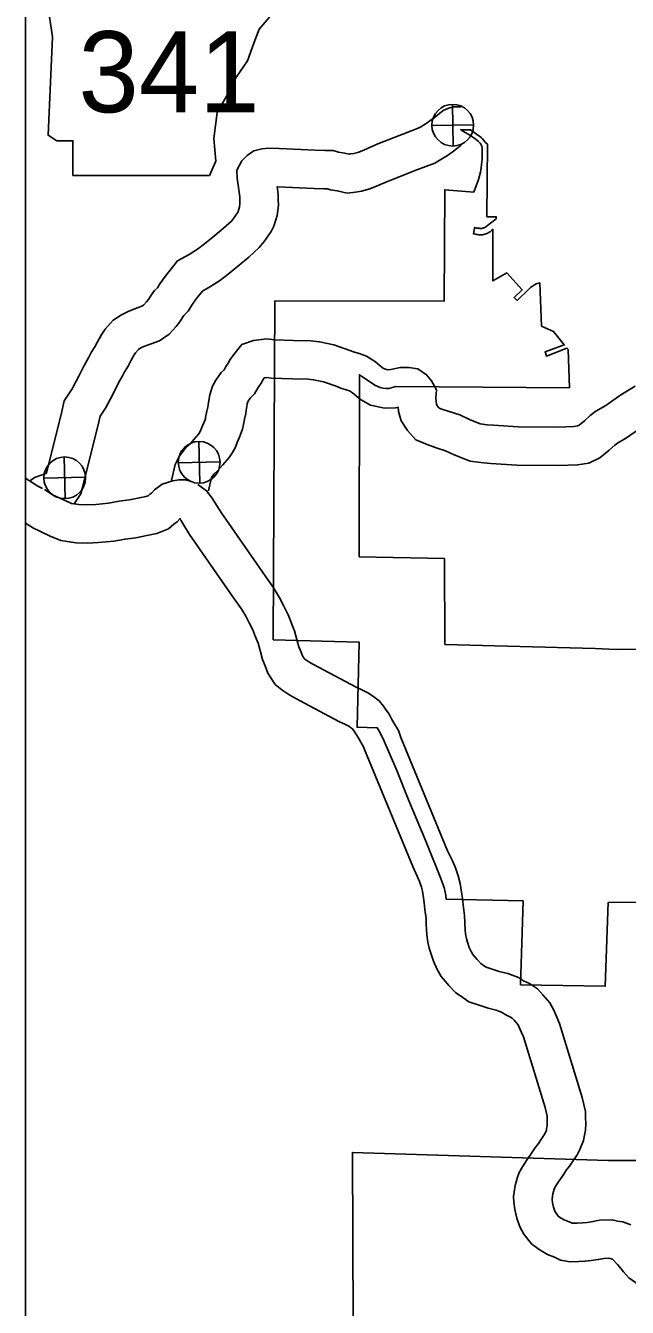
# Model space of a CAD drawing. Extents: x 1377389 to 1380723, y 1168351 to 1170484.
# Drawn here: x 1377549.8 to 1377596.7, y 1170176.4 to 1170276.6 of the extents above; entities that cross this region are included whole.
import ezdxf

# ---------------------------------------------------------------- set-up
doc = ezdxf.new("R2010")
doc.units = 0
doc.layers.add('B_Fill', color=7, linetype='Continuous')
doc.layers.add('B_Text', color=7, linetype='Continuous')

msp = doc.modelspace()

# ---------------------------------------------------------------- linework, layer by layer
at = {"layer": 'B_Fill'}
for p, q in [((1377583.15, 1170267.18), (1377583.08, 1170270.43)), ((1377581.49, 1170268.77), (1377584.74, 1170268.84)), ((1377563.35, 1170240.82), (1377563.27, 1170244.07)), ((1377552.85, 1170239.61), (1377552.77, 1170242.87)), ((1377561.68, 1170242.41), (1377564.94, 1170242.48)), ((1377551.18, 1170241.2), (1377554.44, 1170241.28))]:
    msp.add_line(p, q, dxfattribs=at)
msp.add_lwpolyline([(1377551.09, 1170280.78), (1377551.85, 1170275.7), (1377551.51, 1170268.01), (1377552.19, 1170267.58), (1377553.45, 1170267.58), (1377553.45, 1170264.88), (1377564.11, 1170264.88), (1377564.62, 1170265.98), (1377564.45, 1170267.75), (1377564.7, 1170269.78), (1377565.63, 1170271.39), (1377566.23, 1170272.57), (1377567.07, 1170273.84), (1377567.58, 1170275.2), (1377568, 1170276.3), (1377568.76, 1170277.23), (1377568.93, 1170277.82), (1377568.6, 1170278.24), (1377565.97, 1170278.24), (1377566.57, 1170279.43), (1377566.65, 1170280.19), (1377566.3, 1170280.77)], close=True, dxfattribs=at)
for points in [[(1377550.13, 1170241.03), (1377550.45, 1170241.26), (1377551.04, 1170241.48), (1377551.38, 1170241.6), (1377552.59, 1170246.41), (1377552.77, 1170247.25), (1377553.39, 1170248.19), (1377553.5, 1170248.4), (1377553.91, 1170249.18), (1377554.34, 1170250.03), (1377554.66, 1170250.62), (1377554.87, 1170251.03), (1377555.17, 1170251.48), (1377555.34, 1170251.82), (1377555.66, 1170252.4), (1377555.96, 1170252.85), (1377556.58, 1170253.55), (1377557.23, 1170253.99), (1377557.81, 1170254.27), (1377558.55, 1170254.54), (1377558.84, 1170254.65), (1377558.97, 1170254.74), (1377559.2, 1170254.99), (1377559.34, 1170255.18), (1377559.55, 1170255.51), (1377559.83, 1170255.87), (1377560.05, 1170256.1), (1377560.24, 1170256.41), (1377560.65, 1170256.97), (1377560.84, 1170257.21), (1377561.61, 1170258.19), (1377562.53, 1170258.7), (1377563.18, 1170259.11), (1377563.72, 1170259.52), (1377564.54, 1170260.18), (1377565.21, 1170260.75), (1377565.82, 1170261.31), (1377565.98, 1170261.5), (1377566.34, 1170262.03), (1377566.35, 1170262.06), (1377566.46, 1170262.41), (1377566.49, 1170262.64), (1377566.48, 1170262.9), (1377566.48, 1170263.21), (1377566.27, 1170264.67), (1377566.26, 1170265.28), (1377566.63, 1170266.01), (1377567.05, 1170266.44), (1377567.58, 1170266.79), (1377568.21, 1170266.96), (1377568.74, 1170267), (1377569.55, 1170266.99), (1377572.37, 1170266.84), (1377573.11, 1170266.83), (1377573.76, 1170266.81), (1377574.18, 1170266.7), (1377574.67, 1170266.62), (1377575.03, 1170266.54), (1377575.11, 1170266.55), (1377575.38, 1170266.59), (1377575.69, 1170266.67), (1377576.17, 1170266.86), (1377576.8, 1170267.14), (1377577.39, 1170267.4), (1377579.21, 1170268.1), (1377579.95, 1170268.39), (1377580.42, 1170268.56), (1377580.61, 1170268.67), (1377581.02, 1170268.93), (1377581.31, 1170269.13), (1377581.66, 1170269.38), (1377581.93, 1170269.61), (1377582.35, 1170269.96), (1377582.73, 1170270.11), (1377583.14, 1170270.24), (1377583.52, 1170270.24), (1377583.76, 1170270.24)], [(1377585.09, 1170267.55), (1377584.82, 1170267.77), (1377584.61, 1170267.92), (1377584.32, 1170268.1), (1377584.08, 1170268.24), (1377583.73, 1170268.44), (1377584.5, 1170268.43), (1377584.76, 1170268.25), (1377584.97, 1170268.11), (1377585.07, 1170268.03), (1377585.19, 1170267.93), (1377585.32, 1170267.83), (1377585.41, 1170267.75), (1377585.5, 1170267.64), (1377585.66, 1170267.46), (1377585.81, 1170267.31), (1377585.78, 1170261.64), (1377586.51, 1170261.64), (1377586.51, 1170261.49), (1377585.82, 1170260.95), (1377585.72, 1170260.87), (1377585.69, 1170260.85), (1377585.64, 1170260.82), (1377585.58, 1170260.79), (1377585.53, 1170260.77), (1377585.48, 1170260.75), (1377585.42, 1170260.74), (1377585.4, 1170260.74), (1377585.37, 1170260.73), (1377585.34, 1170260.73), (1377585.31, 1170260.73), (1377585.26, 1170260.73), (1377585.23, 1170260.73), (1377585.18, 1170260.74), (1377585.13, 1170260.74), (1377585.04, 1170260.75), (1377585, 1170260.76), (1377584.94, 1170260.77), (1377584.82, 1170260.81), (1377584.81, 1170260.76), (1377584.79, 1170260.63), (1377584.75, 1170260.43), (1377584.72, 1170260.31), (1377584.82, 1170260.29), (1377584.9, 1170260.27), (1377584.96, 1170260.26), (1377585.02, 1170260.25), (1377585.13, 1170260.24), (1377585.19, 1170260.23), (1377585.23, 1170260.23), (1377585.28, 1170260.23), (1377585.33, 1170260.23), (1377585.38, 1170260.23), (1377585.43, 1170260.23), (1377585.51, 1170260.25), (1377585.61, 1170260.27), (1377585.7, 1170260.3), (1377585.79, 1170260.33), (1377585.88, 1170260.38), (1377585.96, 1170260.43), (1377586.02, 1170260.47), (1377586.14, 1170260.57), (1377586.25, 1170260.66), (1377586.25, 1170256.63), (1377587.32, 1170257.25), (1377588.54, 1170255.94), (1377587.9, 1170255.33), (1377588.13, 1170255.1), (1377589.05, 1170255.99), (1377589.19, 1170256.11), (1377589.34, 1170256.23), (1377589.49, 1170256.33), (1377589.63, 1170256.41), (1377589.7, 1170256.43), (1377589.92, 1170256.47), (1377590.04, 1170253.09), (1377590.98, 1170252.67), (1377591.82, 1170251.63), (1377590.32, 1170251.08), (1377590.43, 1170250.76), (1377592.02, 1170251.38), (1377592.12, 1170251.26), (1377592.22, 1170248.26), (1377578.66, 1170248.38), (1377578.3, 1170248.26), (1377578.11, 1170248.23), (1377577.9, 1170248.22), (1377577.64, 1170248.25), (1377577.43, 1170248.3), (1377577.27, 1170248.37), (1377577.08, 1170248.45), (1377576.88, 1170248.58), (1377576.06, 1170249.13), (1377575.82, 1170249.29), (1377575.8, 1170235.07), (1377582.47, 1170234.93), (1377582.48, 1170228.21)], [(1377553.55, 1170239.26), (1377553.6, 1170239.28), (1377554.07, 1170239.99), (1377554.2, 1170240.49), (1377555.5, 1170245.72), (1377555.58, 1170246.05), (1377556, 1170246.69), (1377556.17, 1170247.03), (1377556.58, 1170247.8), (1377557, 1170248.65), (1377557.31, 1170249.22), (1377557.45, 1170249.48), (1377557.77, 1170249.97), (1377558.01, 1170250.44), (1377558.22, 1170250.84), (1377558.33, 1170251), (1377558.58, 1170251.27), (1377558.74, 1170251.39), (1377558.99, 1170251.51), (1377559.57, 1170251.72), (1377560.2, 1170251.95), (1377560.96, 1170252.46), (1377561.5, 1170253.07), (1377561.79, 1170253.43), (1377562, 1170253.77), (1377562.12, 1170253.92), (1377562.44, 1170254.26), (1377562.73, 1170254.74), (1377563.03, 1170255.15), (1377563.19, 1170255.35), (1377563.59, 1170255.85), (1377564.05, 1170256.11), (1377564.89, 1170256.64), (1377565.56, 1170257.15), (1377566.44, 1170257.86), (1377567.19, 1170258.49), (1377568, 1170259.24), (1377568.39, 1170259.71), (1377568.92, 1170260.49), (1377569.14, 1170260.91), (1377569.4, 1170261.75), (1377569.51, 1170262.54), (1377569.48, 1170262.98), (1377569.48, 1170263.4), (1377569.4, 1170263.99), (1377569.45, 1170263.99), (1377572.28, 1170263.84), (1377573.04, 1170263.83), (1377573.33, 1170263.82), (1377573.55, 1170263.76), (1377574.09, 1170263.67), (1377574.87, 1170263.49), (1377575.51, 1170263.57), (1377575.98, 1170263.64), (1377576.64, 1170263.82), (1377577.34, 1170264.1), (1377578, 1170264.39), (1377578.54, 1170264.62), (1377580.3, 1170265.31), (1377581, 1170265.58), (1377581.7, 1170265.83), (1377582.17, 1170266.11), (1377582.69, 1170266.43), (1377583.05, 1170266.69), (1377583.51, 1170267.02), (1377583.77, 1170267.23)], [(1377601.86, 1170208.09), (1377595.23, 1170208.04), (1377595.02, 1170201.5), (1377588.4, 1170201.61), (1377588.6, 1170208.18), (1377582.6, 1170208.3), (1377582.56, 1170208.6), (1377582.51, 1170208.84), (1377582.43, 1170209.23), (1377582.32, 1170209.55), (1377582.17, 1170209.91), (1377581, 1170212.83), (1377579.64, 1170216.06), (1377578.73, 1170218.35), (1377578.18, 1170219.68), (1377577.76, 1170220.65), (1377577.46, 1170221.25), (1377577.25, 1170221.63), (1377577.21, 1170221.69), (1377575.64, 1170221.74), (1377575.79, 1170228.4), (1377569.09, 1170228.58), (1377569.22, 1170255.08), (1377582.44, 1170255.05), (1377582.48, 1170263.75), (1377584.75, 1170263.57), (1377585.12, 1170264.56), (1377585.2, 1170264.84), (1377585.27, 1170265.13), (1377585.33, 1170265.47), (1377585.36, 1170265.74), (1377585.4, 1170266.14), (1377585.41, 1170266.49), (1377585.41, 1170266.77), (1377585.4, 1170267.03), (1377585.38, 1170267.13), (1377585.35, 1170267.21), (1377585.3, 1170267.32), (1377585.25, 1170267.39), (1377585.09, 1170267.55)], [(1377561.14, 1170241.02), (1377561.43, 1170242.27), (1377561.74, 1170242.91), (1377562.26, 1170243.61), (1377562.63, 1170243.93), (1377562.9, 1170244.24), (1377563.25, 1170244.64), (1377563.32, 1170244.74), (1377563.38, 1170244.87), (1377563.56, 1170245.31), (1377563.69, 1170245.6), (1377563.79, 1170245.85), (1377563.81, 1170245.96), (1377563.91, 1170246.44), (1377563.98, 1170246.77), (1377564.01, 1170246.95), (1377564.06, 1170247.28), (1377564.13, 1170247.73), (1377564.36, 1170248.41), (1377564.62, 1170248.88), (1377565.02, 1170249.46), (1377565.25, 1170249.68), (1377565.39, 1170249.93), (1377565.58, 1170250.2), (1377565.74, 1170250.49), (1377566.01, 1170250.88), (1377566.63, 1170251.66), (1377567.54, 1170251.96), (1377568.6, 1170252.1), (1377569.19, 1170252.02), (1377570.67, 1170251.98), (1377572.01, 1170251.95), (1377572.71, 1170251.88), (1377573.82, 1170251.64), (1377575.08, 1170251.2), (1377575.36, 1170251.08), (1377575.8, 1170250.96), (1377576.38, 1170250.75), (1377577.07, 1170250.3), (1377577.63, 1170249.84), (1377577.77, 1170249.76), (1377578.05, 1170249.69), (1377578.26, 1170249.7), (1377578.99, 1170249.85), (1377579.67, 1170249.87), (1377580.39, 1170249.76), (1377581.06, 1170249.3), (1377581.45, 1170248.83), (1377581.85, 1170248.12), (1377581.79, 1170247.48), (1377581.82, 1170247.22), (1377581.83, 1170246.98), (1377581.84, 1170246.97), (1377581.97, 1170246.76), (1377582.02, 1170246.7), (1377582.18, 1170246.63), (1377582.82, 1170246.42), (1377583.66, 1170246.16), (1377584.41, 1170245.79), (1377585.25, 1170245.46), (1377585.8, 1170245.39), (1377586.28, 1170245.36), (1377588.22, 1170245.22), (1377591.31, 1170245.19), (1377592.55, 1170245.25), (1377592.84, 1170245.29), (1377592.97, 1170245.35), (1377593.39, 1170245.7), (1377593.85, 1170246.1), (1377594.29, 1170246.44), (1377595.05, 1170246.89), (1377596.24, 1170247.73), (1377597.35, 1170248.39)], [(1377564.04, 1170240.23), (1377564.27, 1170241.26), (1377564.31, 1170241.34), (1377564.48, 1170241.56), (1377564.74, 1170241.79), (1377565.15, 1170242.26), (1377565.65, 1170242.83), (1377565.9, 1170243.21), (1377566.11, 1170243.59), (1377566.32, 1170244.12), (1377566.45, 1170244.42), (1377566.7, 1170245.05), (1377566.76, 1170245.41), (1377566.85, 1170245.81), (1377566.94, 1170246.26), (1377566.97, 1170246.5), (1377567.03, 1170246.82), (1377567.06, 1170247.03), (1377567.11, 1170247.19), (1377567.17, 1170247.29), (1377567.31, 1170247.5), (1377567.62, 1170247.8), (1377567.92, 1170248.31), (1377568.14, 1170248.63), (1377568.3, 1170248.92), (1377568.39, 1170249.05), (1377568.6, 1170249.08), (1377568.93, 1170249.03), (1377570.59, 1170248.98), (1377571.82, 1170248.96), (1377572.24, 1170248.91), (1377573.01, 1170248.75), (1377574, 1170248.4), (1377574.37, 1170248.25), (1377574.87, 1170248.1), (1377575.04, 1170248.04), (1377575.29, 1170247.88), (1377575.91, 1170247.36), (1377576.68, 1170246.93), (1377577.78, 1170246.68), (1377578.63, 1170246.72), (1377578.84, 1170246.76), (1377578.86, 1170246.43), (1377579.09, 1170245.7), (1377579.57, 1170244.94), (1377580.23, 1170244.2), (1377581.11, 1170243.83), (1377581.9, 1170243.56), (1377582.55, 1170243.36), (1377583.21, 1170243.04), (1377584.48, 1170242.54), (1377585.5, 1170242.4), (1377586.08, 1170242.36), (1377588.1, 1170242.22), (1377591.36, 1170242.19), (1377592.84, 1170242.26), (1377593.73, 1170242.39), (1377594.59, 1170242.8), (1377595.33, 1170243.41), (1377595.76, 1170243.79), (1377595.98, 1170243.96), (1377596.68, 1170244.37), (1377597.88, 1170245.21)], [(1377549.76, 1170241.24), (1377549.93, 1170241.08), (1377550.26, 1170240.86), (1377550.7, 1170240.59), (1377551.07, 1170240.41)], [(1377551.24, 1170240.32), (1377551.86, 1170239.92), (1377552.14, 1170239.78), (1377552.9, 1170239.43), (1377553.34, 1170239.23), (1377553.91, 1170239.15), (1377554.55, 1170239.14), (1377555.25, 1170239.16), (1377556.23, 1170239.26), (1377557.07, 1170239.41), (1377557.86, 1170239.51), (1377558.64, 1170239.68), (1377559.15, 1170239.77), (1377559.32, 1170239.84), (1377559.46, 1170239.96), (1377559.58, 1170240.05), (1377559.82, 1170240.3), (1377560.43, 1170240.75), (1377561.26, 1170241), (1377561.71, 1170241.07), (1377562.26, 1170241.07), (1377562.77, 1170240.92)], [(1377563.2, 1170240.71), (1377563.87, 1170240.23), (1377564.33, 1170239.65), (1377564.66, 1170239.11), (1377565.07, 1170238.46), (1377565.62, 1170237.66), (1377568.46, 1170233.57), (1377569.08, 1170232.68), (1377569.55, 1170231.92), (1377569.93, 1170231.21), (1377570.25, 1170230.53), (1377570.42, 1170230.13), (1377570.63, 1170229.58), (1377570.75, 1170229.27), (1377570.97, 1170228.51), (1377571.09, 1170228.02), (1377571.25, 1170227.67), (1377571.37, 1170227.32), (1377571.51, 1170227.12), (1377571.57, 1170227.07), (1377571.96, 1170226.8), (1377572.62, 1170226.43), (1377575.57, 1170224.87), (1377576.05, 1170224.64), (1377576.47, 1170224.43), (1377576.84, 1170224.2), (1377577.35, 1170223.81), (1377577.7, 1170223.39), (1377577.85, 1170223.16), (1377578.15, 1170222.77), (1377578.36, 1170222.36), (1377578.51, 1170222.08), (1377578.87, 1170221.49), (1377579.06, 1170220.94), (1377582.71, 1170212.09), (1377583.09, 1170211.3), (1377583.31, 1170210.75), (1377583.53, 1170210.14), (1377583.69, 1170209.54), (1377583.79, 1170208.85), (1377583.86, 1170208.38), (1377583.91, 1170207.85), (1377584.03, 1170207.03), (1377584.04, 1170206.48), (1377584.08, 1170205.82), (1377584.13, 1170205.43), (1377584.17, 1170205.24), (1377584.27, 1170204.94), (1377584.4, 1170204.53), (1377584.55, 1170204.21), (1377584.67, 1170203.99), (1377584.82, 1170203.81), (1377585.02, 1170203.58), (1377585.3, 1170203.28), (1377585.59, 1170203.08), (1377585.71, 1170203), (1377586.19, 1170202.84), (1377586.73, 1170202.66), (1377587.41, 1170202.49), (1377588.23, 1170202.17), (1377588.64, 1170201.93), (1377589.1, 1170201.71), (1377589.72, 1170201.29), (1377590.14, 1170200.84), (1377590.7, 1170200.19), (1377591, 1170199.62), (1377591.23, 1170199.07), (1377591.44, 1170198.6), (1377593.22, 1170192.81), (1377593.47, 1170191.71), (1377593.48, 1170191.25), (1377593.49, 1170190.76), (1377593.47, 1170190.25), (1377593.39, 1170189.86), (1377593.32, 1170189.44), (1377593.04, 1170188.74), (1377592.81, 1170188.32), (1377592.48, 1170187.83), (1377592.22, 1170187.44), (1377591.96, 1170187.12), (1377591.77, 1170186.8), (1377591.42, 1170186.3), (1377591.21, 1170185.98), (1377591.13, 1170185.85), (1377591.05, 1170185.71), (1377591.03, 1170185.64), (1377590.92, 1170185.28), (1377590.87, 1170184.89), (1377590.87, 1170184.83), (1377590.9, 1170184.58), (1377590.98, 1170184.22), (1377591.09, 1170183.92), (1377591.18, 1170183.76), (1377591.35, 1170183.54), (1377591.52, 1170183.41), (1377591.82, 1170183.24), (1377592.2, 1170183.09), (1377592.42, 1170182.99), (1377592.49, 1170182.98), (1377592.82, 1170182.99), (1377593.26, 1170183.01)], [(1377549.76, 1170237.7), (1377550.38, 1170237.3), (1377550.86, 1170237.06), (1377551.67, 1170236.69), (1377552.5, 1170236.33), (1377553.67, 1170236.15), (1377554.57, 1170236.14), (1377555.45, 1170236.17), (1377556.65, 1170236.29), (1377557.52, 1170236.45), (1377558.36, 1170236.55), (1377559.22, 1170236.73), (1377560, 1170236.88), (1377560.9, 1170237.24), (1377561.34, 1170237.62), (1377561.6, 1170237.81), (1377561.8, 1170238.03), (1377561.88, 1170238.05)], [(1377561.86, 1170237.94), (1377561.87, 1170237.92), (1377562.11, 1170237.53), (1377562.56, 1170236.81), (1377563.15, 1170235.95), (1377566, 1170231.85), (1377566.58, 1170231.02), (1377566.94, 1170230.43), (1377567.25, 1170229.86), (1377567.52, 1170229.3), (1377567.64, 1170229), (1377567.84, 1170228.49), (1377567.91, 1170228.32), (1377568.07, 1170227.74), (1377568.24, 1170227.04), (1377568.46, 1170226.55), (1377568.67, 1170225.96), (1377569.25, 1170225.09), (1377569.76, 1170224.67), (1377570.38, 1170224.25), (1377571.19, 1170223.8), (1377574.22, 1170222.19), (1377574.73, 1170221.95), (1377574.99, 1170221.82), (1377575.13, 1170221.73), (1377575.27, 1170221.63), (1377575.28, 1170221.61), (1377575.4, 1170221.43), (1377575.6, 1170221.16), (1377575.71, 1170220.95), (1377575.92, 1170220.57), (1377576.14, 1170220.21), (1377576.26, 1170219.87), (1377579.98, 1170210.86), (1377580.34, 1170210.11), (1377580.5, 1170209.69), (1377580.67, 1170209.24), (1377580.74, 1170208.94), (1377580.82, 1170208.41), (1377580.88, 1170208.02), (1377580.93, 1170207.5), (1377581.03, 1170206.79), (1377581.04, 1170206.36), (1377581.09, 1170205.51), (1377581.17, 1170204.94), (1377581.26, 1170204.47), (1377581.42, 1170204.01), (1377581.6, 1170203.46), (1377581.87, 1170202.85), (1377582.21, 1170202.25), (1377582.55, 1170201.86), (1377582.79, 1170201.57), (1377583.33, 1170201), (1377583.89, 1170200.61), (1377584.37, 1170200.28), (1377585.24, 1170200), (1377585.88, 1170199.78), (1377586.5, 1170199.62), (1377586.92, 1170199.46), (1377587.24, 1170199.27), (1377587.62, 1170199.09), (1377587.75, 1170199), (1377587.9, 1170198.84), (1377588.21, 1170198.48), (1377588.28, 1170198.35), (1377588.47, 1170197.89), (1377588.63, 1170197.54), (1377590.32, 1170192.03), (1377590.48, 1170191.35), (1377590.48, 1170191.21), (1377590.49, 1170190.8), (1377590.48, 1170190.59), (1377590.44, 1170190.38), (1377590.42, 1170190.25), (1377590.33, 1170190.02), (1377590.25, 1170189.88), (1377589.99, 1170189.5), (1377589.8, 1170189.22), (1377589.51, 1170188.85), (1377589.25, 1170188.44), (1377588.93, 1170187.97), (1377588.69, 1170187.6), (1377588.55, 1170187.39), (1377588.3, 1170186.95), (1377588.17, 1170186.57), (1377587.98, 1170185.92), (1377587.86, 1170185.07), (1377587.87, 1170184.61), (1377587.95, 1170184.04), (1377588.1, 1170183.36), (1377588.34, 1170182.7), (1377588.65, 1170182.11), (1377589.25, 1170181.37), (1377589.85, 1170180.91), (1377590.5, 1170180.53), (1377591.04, 1170180.32), (1377591.53, 1170180.1), (1377592.28, 1170179.97), (1377592.95, 1170179.99), (1377593.43, 1170180.02)], [(1377549.76, 1170237.71), (1377549.77, 1170237.71)], [(1377582.48, 1170228.21), (1377594.24, 1170227.89), (1377595.87, 1170227.81), (1377602.49, 1170227.88), (1377602.28, 1170221.26), (1377608.91, 1170221.33), (1377608.7, 1170214.71), (1377615.33, 1170214.78), (1377615.12, 1170208.18), (1377621.75, 1170208.23), (1377621.54, 1170201.62), (1377622.07, 1170181.04)], [(1377601.88, 1170187.89), (1377595.24, 1170187.89), (1377575.27, 1170188.51), (1377575.34, 1170175.2)], [(1377593.25, 1170183.01), (1377593.6, 1170183.04), (1377593.94, 1170183.09), (1377594.57, 1170183.22), (1377595.56, 1170183.25), (1377595.98, 1170183.15), (1377596.39, 1170183.08), (1377597.02, 1170182.86)], [(1377593.44, 1170180.02), (1377593.91, 1170180.05), (1377594.47, 1170180.13), (1377594.93, 1170180.23), (1377595.25, 1170180.24), (1377595.39, 1170180.21), (1377595.57, 1170180.18), (1377595.96, 1170179.74), (1377596.12, 1170179.56), (1377596.45, 1170179.18), (1377596.86, 1170178.7), (1377597.65, 1170178.15), (1377598.1, 1170177.93), (1377598.66, 1170177.69), (1377599.39, 1170177.52), (1377599.72, 1170177.41), (1377600.12, 1170177.26), (1377600.4, 1170177.14), (1377600.49, 1170177.08), (1377600.68, 1170176.9), (1377600.95, 1170176.63), (1377601.11, 1170176.38), (1377601.53, 1170175.79), (1377602.32, 1170174.67)]]:
    msp.add_lwpolyline(points, dxfattribs=at)
for centre in [(1377583.11, 1170268.8), (1377563.31, 1170242.45), (1377552.81, 1170241.24)]:
    msp.add_circle(centre, 1.63, dxfattribs=at)
at = {"layer": 'B_Text'}
msp.add_lwpolyline([(1377549.76, 1170388.77), (1378279.16, 1170388.77), (1378279.16, 1169604.28), (1377549.76, 1169604.28)], close=True, dxfattribs=at)

# ---------------------------------------------------------------- texts
at = {"layer": 'B_Fill'}
msp.add_text('341', height=6.336, dxfattribs=at).set_placement((1377553.88, 1170269.81))

doc.saveas('drawing.dxf')
